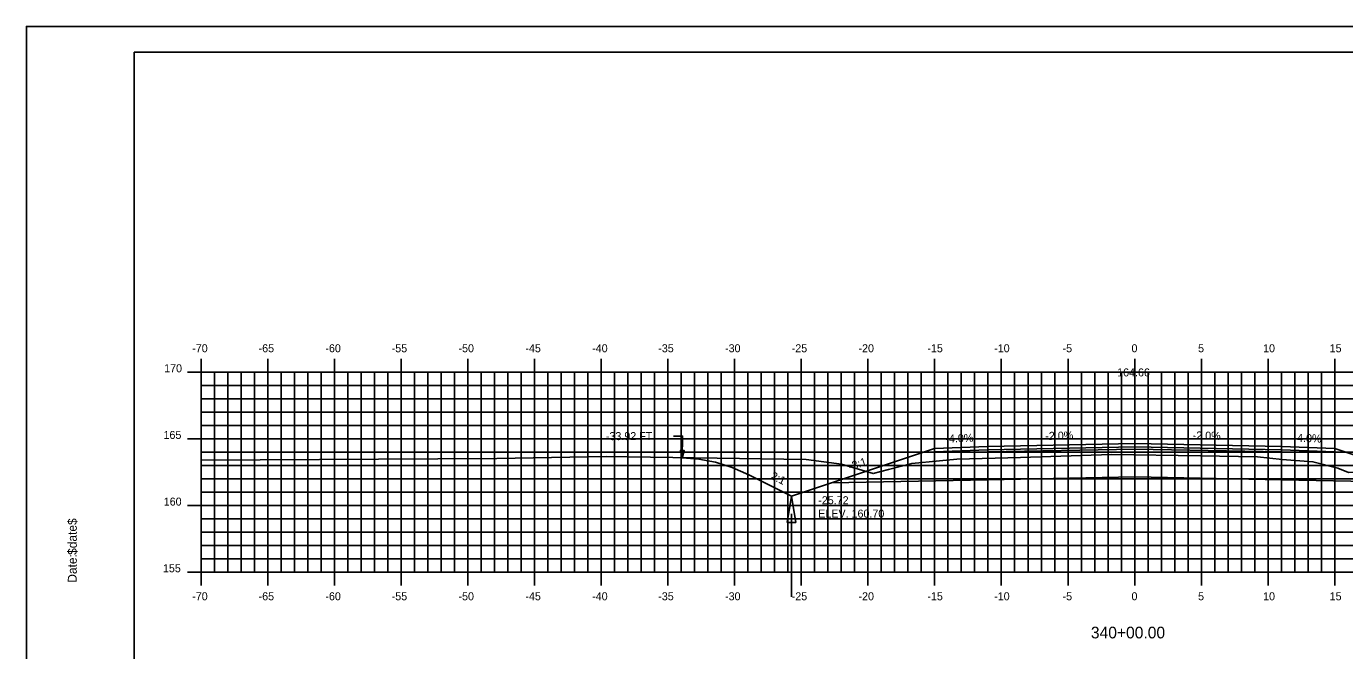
# Model space of a CAD drawing. Extents: x 1142755 to 1142925, y 608981 to 609091.
# Drawn here: x 1142754.7 to 1142853.5, y 609044.5 to 609091.3 of the extents above; entities that cross this region are included whole.
import ezdxf

# ---------------------------------------------------------------- set-up
doc = ezdxf.new("R2010")
doc.units = 0
for name, color, linetype in [('ANNOTATION', 7, 'Continuous'), ('BORDER', 7, 'Continuous'), ('D_Drainage_Ditch_Line', 7, 'Continuous'), ('D_Roadway_Centerline', 7, 'Continuous'), ('D_Roadway_Centerline_Text', 7, 'Continuous'), ('D_Roadway_Edge_Shoulder', 7, 'Continuous'), ('D_Roadway_Edge_TW', 7, 'Continuous'), ('D_Roadway_Pavement', 7, 'Continuous'), ('D_Roadway_SlopeLines', 7, 'Continuous'), ('D_Roadway_SubGrade', 7, 'Continuous'), ('D_Text_Standard', 7, 'Continuous'), ('H_V ANNOTATION', 7, 'Continuous'), ('MAJOR', 7, 'Continuous'), ('MINOR', 7, 'Continuous'), ('PLOT BOUNDARY', 7, 'Continuous'), ('S_Roadway_Centerline', 7, 'Continuous')]:
    doc.layers.add(name, color=color, linetype=linetype)

msp = doc.modelspace()

# ---------------------------------------------------------------- linework, layer by layer
msp.add_lwpolyline([(1142803.888, 609058.924), (1142805.138, 609058.829), (1142806.388, 609058.583), (1142807.638, 609058.185), (1142808.888, 609057.636), (1142812.085, 609056.037), (1142815.085, 609057.037), (1142822.809, 609059.612), (1142822.81, 609059.612), (1142826.81, 609059.772), (1142837.81, 609059.992), (1142848.81, 609059.772), (1142852.81, 609059.612), (1142860.533, 609057.037), (1142863.533, 609056.037), (1142865.53, 609057.036), (1142866.78, 609057.581), (1142868.03, 609057.965), (1142869.28, 609058.189), (1142870.53, 609058.252)])
at = {"layer": 'BORDER'}
msp.add_lwpolyline([(1142762.81, 608984.335), (1142922.81, 608984.335), (1142922.81, 609089.335), (1142762.81, 609089.335)], close=True, dxfattribs=at)
at = {"layer": 'D_Drainage_Ditch_Line'}
msp.add_line((1142812.085, 609054.725), (1142812.085, 609048.482), dxfattribs=at)
msp.add_lwpolyline([(1142812.413, 609054.069), (1142811.757, 609054.069), (1142812.085, 609056.037)], close=True, dxfattribs=at)
at = {"layer": 'D_Roadway_Edge_Shoulder'}
for points in [[(1142826.81, 609059.772), (1142822.81, 609059.612), (1142822.81, 609059.362), (1142826.81, 609059.522)], [(1142848.81, 609059.772), (1142852.81, 609059.612), (1142852.81, 609059.362), (1142848.81, 609059.522)]]:
    msp.add_lwpolyline(points, close=True, dxfattribs=at)
at = {"layer": 'D_Roadway_Edge_TW'}
msp.add_lwpolyline([(1142826.81, 609059.522), (1142826.81, 609059.772), (1142837.81, 609059.992), (1142848.81, 609059.772), (1142848.81, 609059.522), (1142837.81, 609059.742)], close=True, dxfattribs=at)
at = {"layer": 'D_Roadway_Pavement'}
msp.add_lwpolyline([(1142826.81, 609059.355), (1142826.81, 609059.522), (1142837.81, 609059.742), (1142848.81, 609059.522), (1142848.81, 609059.355), (1142837.81, 609059.575)], close=True, dxfattribs=at)
at = {"layer": 'D_Roadway_SlopeLines'}
for points in [[(1142812.085, 609056.037), (1142808.888, 609057.636), (1142807.638, 609058.185), (1142806.388, 609058.583), (1142805.138, 609058.829), (1142803.888, 609058.924)], [(1142815.085, 609057.037), (1142812.085, 609056.037)]]:
    msp.add_lwpolyline(points, dxfattribs=at)
at = {"layer": 'D_Roadway_SubGrade'}
for points in [[(1142826.81, 609059.355), (1142826.81, 609059.522), (1142822.81, 609059.362), (1142822.81, 609059.612), (1142822.809, 609059.612), (1142815.085, 609057.037), (1142826.81, 609057.272)], [(1142826.81, 609057.272), (1142826.81, 609059.355), (1142837.81, 609059.575), (1142848.81, 609059.355), (1142848.81, 609057.272), (1142837.81, 609057.492)], [(1142848.81, 609059.355), (1142848.81, 609059.522), (1142852.81, 609059.362), (1142852.81, 609059.612), (1142852.81, 609059.612), (1142860.533, 609057.037), (1142848.81, 609057.272)]]:
    msp.add_lwpolyline(points, close=True, dxfattribs=at)
at = {"layer": 'D_Text_Standard'}
msp.add_lwpolyline([(1142803.888, 609058.886), (1142803.912, 609060.546), (1142803.232, 609060.546)], dxfattribs=at)
msp.add_lwpolyline([(1142803.888, 609058.886), (1142803.751, 609059.47), (1142804.042, 609059.466)], close=True, dxfattribs=at)
at = {"layer": 'MAJOR'}
for p, q in [((1142767.81, 609066.337), (1142767.81, 609065.335)), ((1142772.81, 609066.337), (1142772.81, 609065.335)), ((1142777.81, 609066.337), (1142777.81, 609065.335)), ((1142782.81, 609066.337), (1142782.81, 609065.335)), ((1142787.81, 609066.337), (1142787.81, 609065.335)), ((1142792.81, 609066.337), (1142792.81, 609065.335)), ((1142797.81, 609066.337), (1142797.81, 609065.335)), ((1142802.81, 609066.337), (1142802.81, 609065.335)), ((1142807.81, 609066.337), (1142807.81, 609065.335)), ((1142812.81, 609066.337), (1142812.81, 609065.335)), ((1142817.81, 609066.337), (1142817.81, 609065.335)), ((1142822.81, 609066.337), (1142822.81, 609065.335)), ((1142827.81, 609066.337), (1142827.81, 609065.335)), ((1142832.81, 609066.337), (1142832.81, 609065.335)), ((1142837.81, 609066.337), (1142837.81, 609065.335)), ((1142842.81, 609066.337), (1142842.81, 609065.335)), ((1142847.81, 609066.337), (1142847.81, 609065.335)), ((1142852.81, 609066.337), (1142852.81, 609065.335)), ((1142766.808, 609065.335), (1142767.81, 609065.335)), ((1142767.81, 609065.335), (1142907.81, 609065.335)), ((1142767.81, 609050.335), (1142767.81, 609065.335)), ((1142767.81, 609050.335), (1142767.81, 609065.335)), ((1142767.81, 609065.335), (1142907.81, 609065.335)), ((1142772.81, 609050.335), (1142772.81, 609065.335)), ((1142777.81, 609050.335), (1142777.81, 609065.335)), ((1142782.81, 609050.335), (1142782.81, 609065.335)), ((1142787.81, 609050.335), (1142787.81, 609065.335)), ((1142792.81, 609050.335), (1142792.81, 609065.335)), ((1142797.81, 609050.335), (1142797.81, 609065.335)), ((1142802.81, 609050.335), (1142802.81, 609065.335)), ((1142807.81, 609050.335), (1142807.81, 609065.335)), ((1142812.81, 609050.335), (1142812.81, 609065.335)), ((1142817.81, 609050.335), (1142817.81, 609065.335)), ((1142822.81, 609050.335), (1142822.81, 609065.335)), ((1142827.81, 609050.335), (1142827.81, 609065.335)), ((1142832.81, 609050.335), (1142832.81, 609065.335)), ((1142837.81, 609050.335), (1142837.81, 609065.335)), ((1142842.81, 609050.335), (1142842.81, 609065.335)), ((1142847.81, 609050.335), (1142847.81, 609065.335)), ((1142852.81, 609050.335), (1142852.81, 609065.335)), ((1142766.808, 609060.335), (1142767.81, 609060.335)), ((1142767.81, 609060.335), (1142907.81, 609060.335)), ((1142766.808, 609055.335), (1142767.81, 609055.335)), ((1142767.81, 609055.335), (1142907.81, 609055.335)), ((1142766.808, 609050.335), (1142767.81, 609050.335)), ((1142767.81, 609050.335), (1142907.81, 609050.335)), ((1142767.81, 609050.335), (1142907.81, 609050.335)), ((1142767.81, 609049.333), (1142767.81, 609050.335)), ((1142772.81, 609049.333), (1142772.81, 609050.335)), ((1142777.81, 609049.333), (1142777.81, 609050.335)), ((1142782.81, 609049.333), (1142782.81, 609050.335)), ((1142787.81, 609049.333), (1142787.81, 609050.335)), ((1142792.81, 609049.333), (1142792.81, 609050.335)), ((1142797.81, 609049.333), (1142797.81, 609050.335)), ((1142802.81, 609049.333), (1142802.81, 609050.335)), ((1142807.81, 609049.333), (1142807.81, 609050.335)), ((1142812.81, 609049.333), (1142812.81, 609050.335)), ((1142817.81, 609049.333), (1142817.81, 609050.335)), ((1142822.81, 609049.333), (1142822.81, 609050.335)), ((1142827.81, 609049.333), (1142827.81, 609050.335)), ((1142832.81, 609049.333), (1142832.81, 609050.335)), ((1142837.81, 609049.333), (1142837.81, 609050.335)), ((1142842.81, 609049.333), (1142842.81, 609050.335)), ((1142847.81, 609049.333), (1142847.81, 609050.335)), ((1142852.81, 609049.333), (1142852.81, 609050.335))]:
    msp.add_line(p, q, dxfattribs=at)
at = {"layer": 'MINOR'}
for p, q in [((1142768.81, 609050.335), (1142768.81, 609065.335)), ((1142769.81, 609050.335), (1142769.81, 609065.335)), ((1142770.81, 609050.335), (1142770.81, 609065.335)), ((1142771.81, 609050.335), (1142771.81, 609065.335)), ((1142773.81, 609050.335), (1142773.81, 609065.335)), ((1142774.81, 609050.335), (1142774.81, 609065.335)), ((1142775.81, 609050.335), (1142775.81, 609065.335)), ((1142776.81, 609050.335), (1142776.81, 609065.335)), ((1142778.81, 609050.335), (1142778.81, 609065.335)), ((1142779.81, 609050.335), (1142779.81, 609065.335)), ((1142780.81, 609050.335), (1142780.81, 609065.335)), ((1142781.81, 609050.335), (1142781.81, 609065.335)), ((1142783.81, 609050.335), (1142783.81, 609065.335)), ((1142784.81, 609050.335), (1142784.81, 609065.335)), ((1142785.81, 609050.335), (1142785.81, 609065.335)), ((1142786.81, 609050.335), (1142786.81, 609065.335)), ((1142788.81, 609050.335), (1142788.81, 609065.335)), ((1142789.81, 609050.335), (1142789.81, 609065.335)), ((1142790.81, 609050.335), (1142790.81, 609065.335)), ((1142791.81, 609050.335), (1142791.81, 609065.335)), ((1142793.81, 609050.335), (1142793.81, 609065.335)), ((1142794.81, 609050.335), (1142794.81, 609065.335)), ((1142795.81, 609050.335), (1142795.81, 609065.335)), ((1142796.81, 609050.335), (1142796.81, 609065.335)), ((1142798.81, 609050.335), (1142798.81, 609065.335)), ((1142799.81, 609050.335), (1142799.81, 609065.335)), ((1142800.81, 609050.335), (1142800.81, 609065.335)), ((1142801.81, 609050.335), (1142801.81, 609065.335)), ((1142803.81, 609050.335), (1142803.81, 609065.335)), ((1142804.81, 609050.335), (1142804.81, 609065.335)), ((1142805.81, 609050.335), (1142805.81, 609065.335)), ((1142806.81, 609050.335), (1142806.81, 609065.335)), ((1142808.81, 609050.335), (1142808.81, 609065.335)), ((1142809.81, 609050.335), (1142809.81, 609065.335)), ((1142810.81, 609050.335), (1142810.81, 609065.335)), ((1142811.81, 609050.335), (1142811.81, 609065.335)), ((1142813.81, 609050.335), (1142813.81, 609065.335)), ((1142814.81, 609050.335), (1142814.81, 609065.335)), ((1142815.81, 609050.335), (1142815.81, 609065.335)), ((1142816.81, 609050.335), (1142816.81, 609065.335)), ((1142818.81, 609050.335), (1142818.81, 609065.335)), ((1142819.81, 609050.335), (1142819.81, 609065.335)), ((1142820.81, 609050.335), (1142820.81, 609065.335)), ((1142821.81, 609050.335), (1142821.81, 609065.335)), ((1142823.81, 609050.335), (1142823.81, 609065.335)), ((1142824.81, 609050.335), (1142824.81, 609065.335)), ((1142825.81, 609050.335), (1142825.81, 609065.335)), ((1142826.81, 609050.335), (1142826.81, 609065.335)), ((1142828.81, 609050.335), (1142828.81, 609065.335)), ((1142829.81, 609050.335), (1142829.81, 609065.335)), ((1142830.81, 609050.335), (1142830.81, 609065.335)), ((1142831.81, 609050.335), (1142831.81, 609065.335)), ((1142833.81, 609050.335), (1142833.81, 609065.335)), ((1142834.81, 609050.335), (1142834.81, 609065.335)), ((1142835.81, 609050.335), (1142835.81, 609065.335)), ((1142836.81, 609050.335), (1142836.81, 609065.335)), ((1142838.81, 609050.335), (1142838.81, 609065.335)), ((1142839.81, 609050.335), (1142839.81, 609065.335)), ((1142840.81, 609050.335), (1142840.81, 609065.335)), ((1142841.81, 609050.335), (1142841.81, 609065.335)), ((1142843.81, 609050.335), (1142843.81, 609065.335)), ((1142844.81, 609050.335), (1142844.81, 609065.335)), ((1142845.81, 609050.335), (1142845.81, 609065.335)), ((1142846.81, 609050.335), (1142846.81, 609065.335)), ((1142848.81, 609050.335), (1142848.81, 609065.335)), ((1142849.81, 609050.335), (1142849.81, 609065.335)), ((1142850.81, 609050.335), (1142850.81, 609065.335)), ((1142851.81, 609050.335), (1142851.81, 609065.335)), ((1142767.81, 609064.335), (1142907.81, 609064.335)), ((1142767.81, 609064.335), (1142768.812, 609064.335)), ((1142767.81, 609063.335), (1142907.81, 609063.335)), ((1142767.81, 609063.335), (1142768.812, 609063.335)), ((1142767.81, 609062.335), (1142907.81, 609062.335)), ((1142767.81, 609062.335), (1142768.812, 609062.335)), ((1142767.81, 609061.335), (1142907.81, 609061.335)), ((1142767.81, 609061.335), (1142768.812, 609061.335)), ((1142767.81, 609059.335), (1142907.81, 609059.335)), ((1142767.81, 609059.335), (1142768.812, 609059.335)), ((1142767.81, 609058.335), (1142907.81, 609058.335)), ((1142767.81, 609058.335), (1142768.812, 609058.335)), ((1142767.81, 609057.335), (1142907.81, 609057.335)), ((1142767.81, 609057.335), (1142768.812, 609057.335)), ((1142767.81, 609056.335), (1142907.81, 609056.335)), ((1142767.81, 609056.335), (1142768.812, 609056.335)), ((1142767.81, 609054.335), (1142907.81, 609054.335)), ((1142767.81, 609054.335), (1142768.812, 609054.335)), ((1142767.81, 609053.335), (1142907.81, 609053.335)), ((1142767.81, 609053.335), (1142768.812, 609053.335)), ((1142767.81, 609052.335), (1142907.81, 609052.335)), ((1142767.81, 609052.335), (1142768.812, 609052.335)), ((1142767.81, 609051.335), (1142907.81, 609051.335)), ((1142767.81, 609051.335), (1142768.812, 609051.335))]:
    msp.add_line(p, q, dxfattribs=at)
at = {"layer": 'PLOT BOUNDARY'}
msp.add_lwpolyline([(1142754.717, 608981.276), (1142924.717, 608981.276), (1142924.717, 609091.276), (1142754.717, 609091.276)], close=True, dxfattribs=at)
at = {"layer": 'S_Roadway_Centerline'}
msp.add_lwpolyline([(1142767.81, 609058.735), (1142789.999, 609058.859), (1142798.177, 609059.01), (1142813.177, 609058.784), (1142815.825, 609058.433), (1142818.214, 609057.737), (1142819.359, 609058.049), (1142821.097, 609058.497), (1142823.175, 609058.691), (1142824.483, 609058.817), (1142829.243, 609058.936), (1142836.068, 609059.165), (1142842.737, 609059.067), (1142847.022, 609058.992), (1142848.858, 609058.805), (1142851.167, 609058.627), (1142853.046, 609058.141), (1142853.844, 609057.819), (1142857.677, 609058.043), (1142859.813, 609058.396), (1142876.869, 609058.167), (1142887.187, 609058.09), (1142907.81, 609057.874)], dxfattribs=at)

# ---------------------------------------------------------------- texts
at = {"layer": 'ANNOTATION'}
for s, rotation, p in [('-4.0%', 2.29061, (1142823.626, 609060.045)), ('-2.0%', 1.14576, (1142831.113, 609060.258)), ('-2.0%', 358.85424, (1142842.153, 609060.305)), ('-4.0%', 357.70939, (1142849.706, 609060.137)), ('-3:1', 18.43482, (1142816.464, 609057.951)), ('2:1', 333.43495, (1142810.454, 609057.371))]:
    msp.add_text(s, height=0.6, rotation=rotation, dxfattribs=at).set_placement(p)
at = {"layer": 'BORDER'}
for s, p in [('$date$', (1142758.495, 609051.64)), ('Date:', (1142758.495, 609049.552))]:
    msp.add_text(s, height=0.6696, rotation=90, dxfattribs=at).set_placement(p)
at = {"layer": 'D_Roadway_Centerline'}
for s, p in [('C', (1142837.805, 609059.992)), ('L', (1142837.81, 609059.985))]:
    msp.add_text(s, height=0.0146, dxfattribs=at).set_placement(p)
at = {"layer": 'D_Roadway_Centerline_Text'}
msp.add_text('164.66', height=0.6, dxfattribs=at).set_placement((1142836.494, 609065.024))
at = {"layer": 'D_Text_Standard'}
for s, p in [('-33.92 FT', (1142798.163, 609060.246)), ('-25.72', (1142814.085, 609055.437)), ('ELEV. 160.70', (1142814.085, 609054.435))]:
    msp.add_text(s, height=0.6, dxfattribs=at).set_placement(p)
at = {"layer": 'H_V ANNOTATION'}
for s, height, p in [('-70', 0.6, (1142767.152, 609066.835)), ('-65', 0.6, (1142772.128, 609066.835)), ('-60', 0.6, (1142777.136, 609066.835)), ('-55', 0.6, (1142782.106, 609066.835)), ('-50', 0.6, (1142787.114, 609066.835)), ('-45', 0.6, (1142792.128, 609066.835)), ('-40', 0.6, (1142797.136, 609066.835)), ('-35', 0.6, (1142802.09, 609066.835)), ('-30', 0.6, (1142807.098, 609066.835)), ('-25', 0.6, (1142812.095, 609066.835)), ('-20', 0.6, (1142817.103, 609066.835)), ('-15', 0.6, (1142822.267, 609066.835)), ('-10', 0.6, (1142827.275, 609066.835)), ('-5', 0.6, (1142832.401, 609066.835)), ('0', 0.6, (1142837.569, 609066.835)), ('5', 0.6, (1142842.561, 609066.835)), ('10', 0.6, (1142847.435, 609066.835)), ('15', 0.6, (1142852.427, 609066.835)), ('170', 0.6, (1142765.047, 609065.335)), ('165', 0.6, (1142764.999, 609060.335)), ('160', 0.6, (1142765.015, 609055.335)), ('155', 0.6, (1142764.956, 609050.335)), ('-70', 0.6, (1142767.152, 609048.235)), ('-65', 0.6, (1142772.128, 609048.235)), ('-60', 0.6, (1142777.136, 609048.235)), ('-55', 0.6, (1142782.106, 609048.235)), ('-50', 0.6, (1142787.114, 609048.235)), ('-45', 0.6, (1142792.128, 609048.235)), ('-40', 0.6, (1142797.136, 609048.235)), ('-35', 0.6, (1142802.09, 609048.235)), ('-30', 0.6, (1142807.098, 609048.235)), ('-25', 0.6, (1142812.095, 609048.235)), ('-20', 0.6, (1142817.103, 609048.235)), ('-15', 0.6, (1142822.267, 609048.235)), ('-10', 0.6, (1142827.275, 609048.235)), ('-5', 0.6, (1142832.401, 609048.235)), ('0', 0.6, (1142837.569, 609048.235)), ('5', 0.6, (1142842.561, 609048.235)), ('10', 0.6, (1142847.435, 609048.235)), ('15', 0.6, (1142852.427, 609048.235)), ('340+00.00', 0.875, (1142834.525, 609045.378))]:
    msp.add_text(s, height=height, dxfattribs=at).set_placement(p)
at = {"layer": 'MAJOR'}
msp.add_text('-', height=0.006, dxfattribs=at).set_placement((1142767.806, 609050.335))
at = {"layer": 'S_Roadway_Centerline'}
for s, p in [('L', (1142836.06, 609059.158)), ('C', (1142836.063, 609059.165))]:
    msp.add_text(s, height=0.0146, dxfattribs=at).set_placement(p)

doc.saveas('drawing.dxf')
